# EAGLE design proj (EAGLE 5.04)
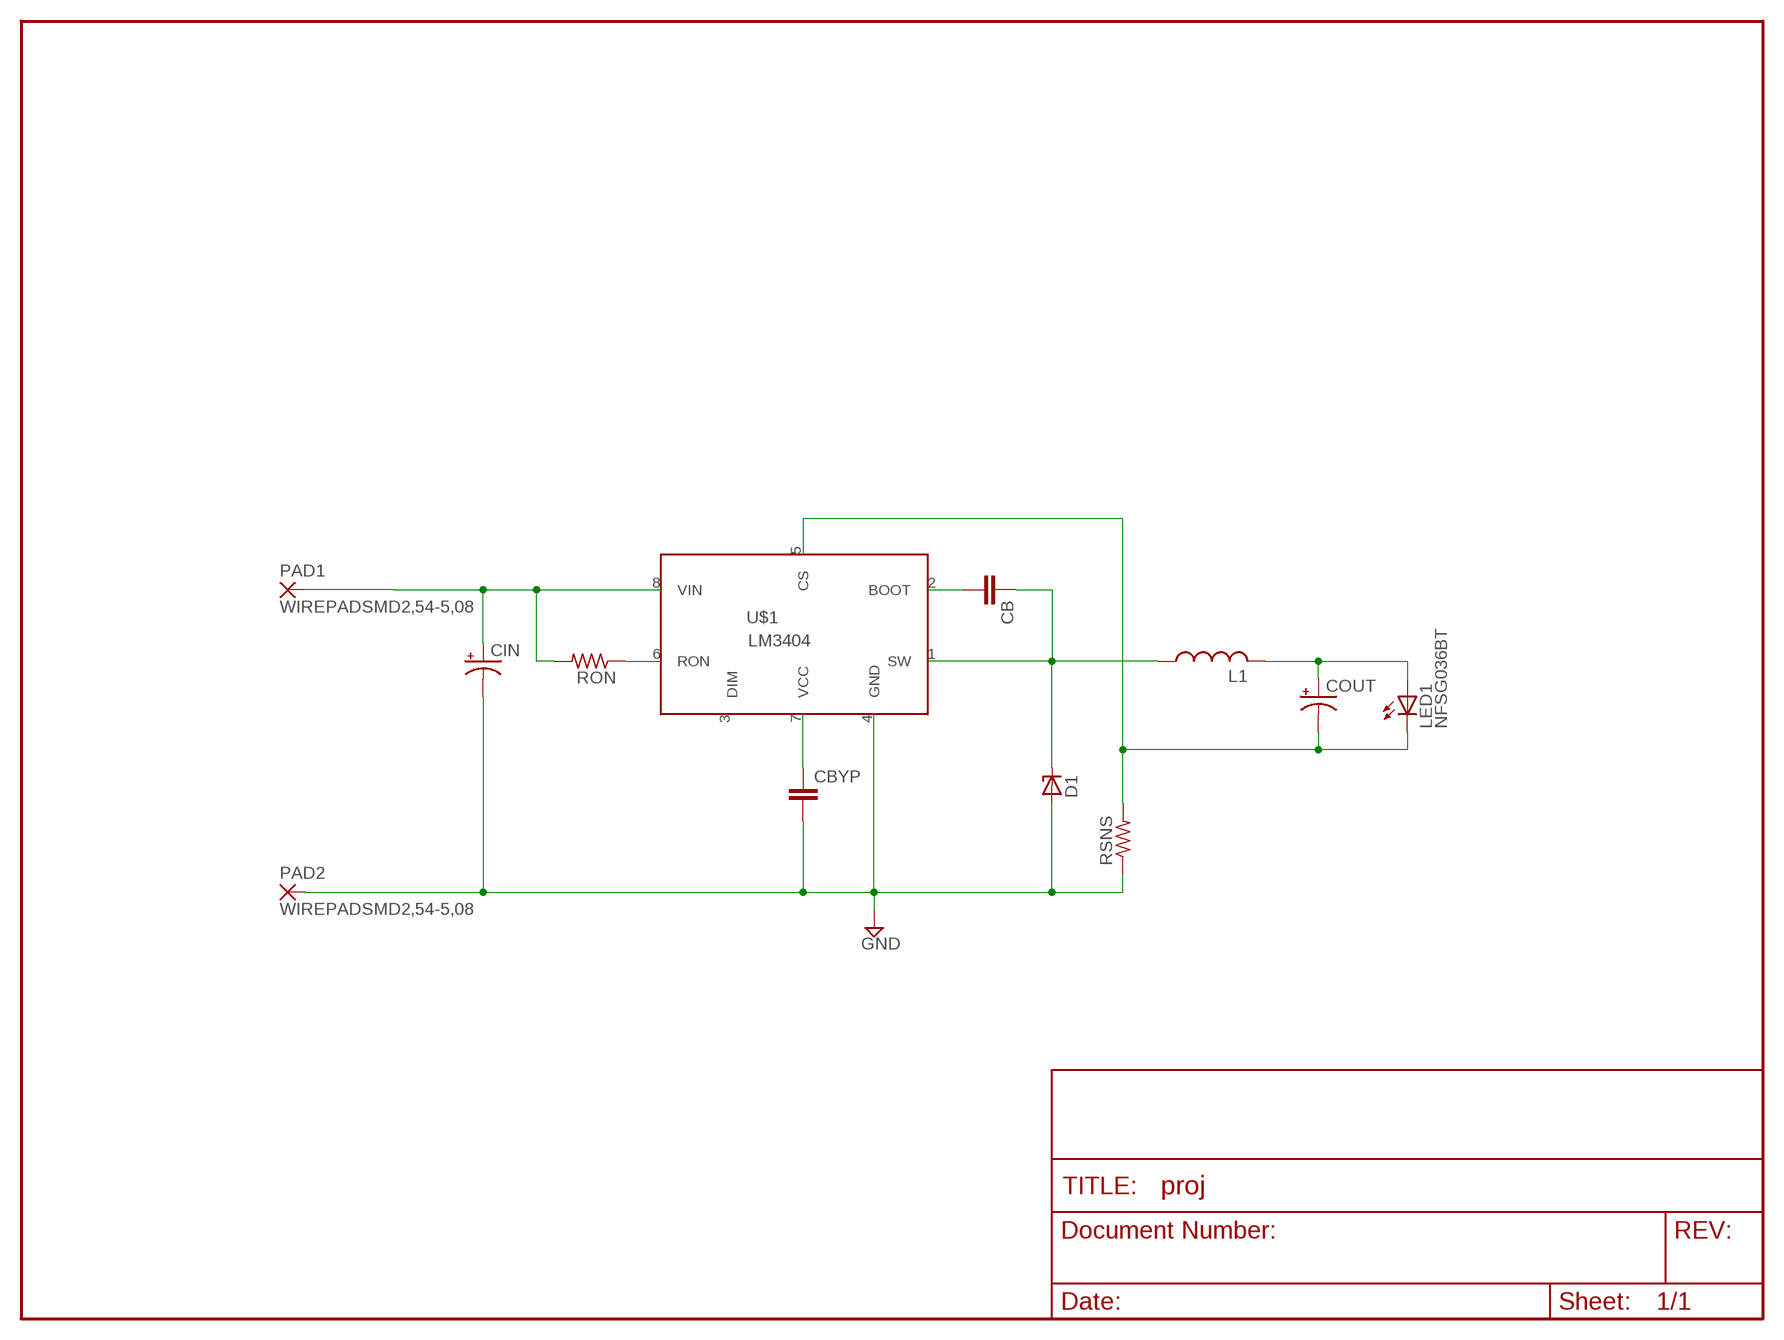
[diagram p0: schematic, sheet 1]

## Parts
CB  C-EUC0603K  [C0603K]
CBYP  C-EUC0805K  [C0805K]
CIN  CPOL-USD/7343-31R  [D/7343-31R]
COUT  CPOL-USC  [PANASONIC_C]
D1  ZENER-DIODESMB  [SMB]
L1  L-USWE-TPC  [POWER-CHOKE_WE-TPC]
LED1  NFSG036BT  [NFSG036BT]
PAD1  WIREPADSMD2,54-5,08  [SMD2,54-5,08]
PAD2  WIREPADSMD2,54-5,08  [SMD2,54-5,08]
RON  R-US_M5923  [M5923]
RSNS  R-US_M5923  [M5923]
U$1  LM3404  [8SOIC]

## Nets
GND: CBYP.2 CIN.- D1.A PAD2.1(P) RSNS.1 U$1.4(GND)
N$1: CIN.+ PAD1.1(P) RON.2 U$1.8(VIN)
N$2: RON.1 U$1.6(RON)
N$3: CBYP.1 U$1.7(VCC)
N$4: CB.1 D1.C L1.1 U$1.1(SW)
N$5: CB.2 U$1.2(BOOT)
N$7: COUT.+ L1.2 LED1.A
N$8: COUT.- LED1.C RSNS.2 U$1.5(CS)
Unconnected: U$1.3(DIM)

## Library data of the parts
CB CBYP = resistor:C-EU: CAPACITOR, European symbol
CIN COUT = rcl:CPOL-US: POLARIZED CAPACITOR, American symbol
D1 = diode:ZENER-DIODE: Z-Diode
L1 = rcl:L-US: INDUCTOR, American symbol
LED1 = led:NFSG036BT: CHIP TYPE GREEN LED NFSx036xT
PAD1 PAD2 = wirepad:WIREPAD: Wire PAD connect wire on PCB
RON RSNS = resistor:R-US_: RESISTOR, American symbol
U$1 = trl:LM3404

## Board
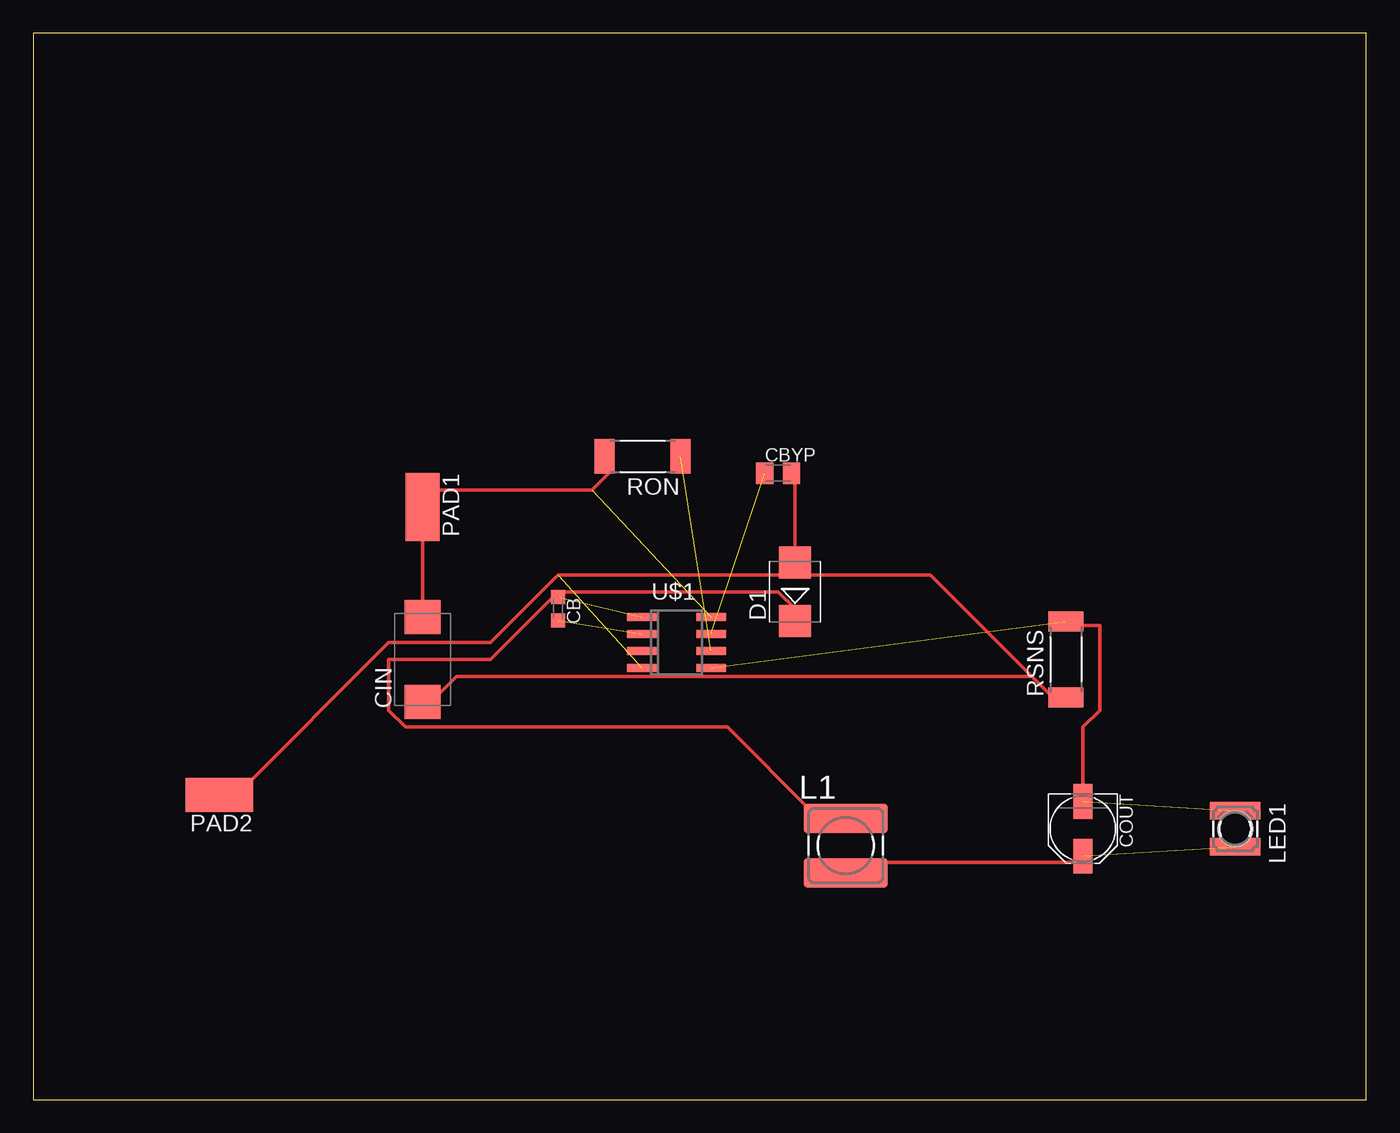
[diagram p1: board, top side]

Size 100 x 80 mm. Coordinates in mm from the lower left corner, seen from the top.
Outline: 0,0 100,0 100,80 0,80 0,0
Copper layers (1*16): Top 0.035mm / dielectric 1.5mm / Bottom 0.035mm
Design rules "default": minimum track width 10mil, minimum drill 24mil, track to track 8mil, track to pad 8mil, pad to pad 8mil, via to via 8mil, smd to smd 8mil, copper to edge 40mil, drill to drill 8mil, minimum pad ring 10mil, minimum via ring 8mil, stop-mask expansion 4mil, vias tented up to drill 0mil, thermal gap 10mil

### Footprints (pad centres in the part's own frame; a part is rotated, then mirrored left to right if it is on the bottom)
C0603K = smd 1.05 x 1.08: 1 -0.875,0; 2 0.875,0
C0805K = smd 1.3 x 1.6: 1 -1,0; 2 1,0
D/7343-31R = smd 2.55 x 2.7: + 3.175,0; - -3.175,0
PANASONIC_C = smd 2.6 x 1.4: + 2.05,0; - -2.05,0
SMB = smd 2.4 x 2.4: A 2.2,0; C -2.2,0
POWER-CHOKE_WE-TPC = smd 6.3 x 2.2: 1 0,2.05; 2 0,-2.05
NFSG036BT = smd 1.3 x 3.8: A 1.35,0; C -1.35,0 | hole 2.6: 0,0
SMD2,54-5,08 = smd 2.54 x 5.08: 1 0,0
M5923 = smd 1.5 x 2.6: 1 -2.85,0; 2 2.85,0
8SOIC = smd 0.6 x 2.2: 1 -1.905,-2.6; 2 -0.635,-2.6; 3 0.635,-2.6; 4 1.905,-2.6; 5 1.905,2.6; 6 0.635,2.6; 7 -0.635,2.6; 8 -1.905,2.6

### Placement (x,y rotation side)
CB  39.37,36.83 270 top
CBYP  55.88,46.99 0 top
CIN  29.21,33.02 90 top
COUT  78.74,20.32 270 top
D1  57.15,38.1 90 top
L1  60.96,19.05 0 top
LED1  90.17,20.32 270 top
PAD1  29.21,44.45 180 top
PAD2  13.97,22.86 90 top
RON  45.72,48.26 180 top
RSNS  77.47,33.02 90 top
U$1  48.26,34.29 270 top

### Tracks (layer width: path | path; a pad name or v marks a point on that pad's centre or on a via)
GND  (1 unrouted)
  Top 0.254: CBYP.2 57.15,46.99 57.15,40.64 D1.A | 74.93,31.75 67.31,39.37 57.15,39.37 | 74.93,31.75 76.2,30.48 RSNS.1 | 57.15,39.37 D1.A | 74.93,31.75 31.75,31.75 30.48,30.48 CIN.- | 57.15,39.37 39.37,39.37 34.29,34.29 26.67,34.29 15.24,22.86 PAD2.1 | 57.15,39.37 D1.A
N$1  (1 unrouted)
  Top 0.254: RON.2 43.18,46.99 41.91,45.72 29.21,45.72 PAD1.1 29.21,43.18 29.21,36.83 CIN.+
N$2  (1 unrouted)
N$3  (1 unrouted)
N$4  (1 unrouted)
  Top 0.254: 39.37,38.1 55.88,38.1 57.15,36.83 D1.C | 39.37,38.1 CB.1 39.37,38.1 | 39.37,38.1 34.29,33.02 26.67,33.02 26.67,29.21 27.94,27.94 52.07,27.94 58.42,21.59 L1.1
N$5  (1 unrouted)
N$7  (1 unrouted)
  Top 0.254: COUT.+ 78.74,17.78 63.5,17.78 L1.2
N$8  (2 unrouted)
  Top 0.254: COUT.- 78.74,22.86 78.74,27.94 80.01,29.21 80.01,35.56 78.74,35.56 RSNS.2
